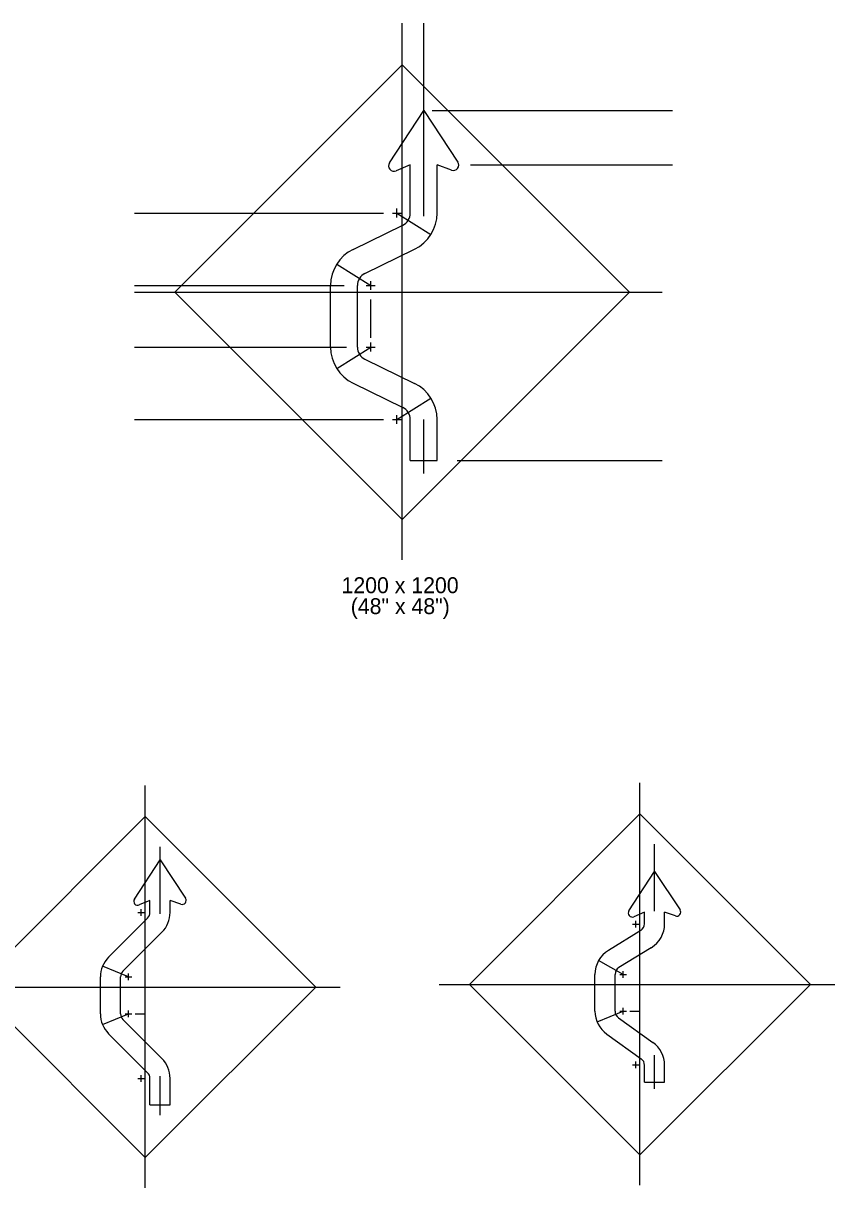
# Model space of a CAD drawing. Extents: x 0 to 0.249, y -0.213 to 0.259.
# Drawn here: x 0.1279 to 0.249, y -0.1781 to -0.0043 of the extents above; entities that cross this region are included whole.
import ezdxf

# ---------------------------------------------------------------- set-up
doc = ezdxf.new("R2010")
doc.units = 0
doc.layers.add('1', color=7, linetype='Continuous')
doc.layers.add('3', color=7, linetype='Continuous')

msp = doc.modelspace()

# ---------------------------------------------------------------- linework, layer by layer
at = {"layer": '1'}
for p, q in [((0.18253828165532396, -0.02516510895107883), (0.18764227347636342, -0.017349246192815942)), ((0.18764227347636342, -0.017349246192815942), (0.19273947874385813, -0.02503121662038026)), ((0.18891761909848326, -0.017334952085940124), (0.22476879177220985, -0.017334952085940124)), ((0.18564227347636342, -0.025454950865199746), (0.1835158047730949, -0.026340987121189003)), ((0.18564227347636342, -0.03264923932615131), (0.18564227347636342, -0.025454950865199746)), ((0.19180380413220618, -0.026226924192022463), (0.18964227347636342, -0.025454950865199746)), ((0.18964227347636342, -0.03264923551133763), (0.18964227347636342, -0.025454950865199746)), ((0.1946373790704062, -0.025454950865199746), (0.22476879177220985, -0.025454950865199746)), ((0.14447220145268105, -0.03264924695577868), (0.18163737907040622, -0.03264924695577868)), ((0.1829756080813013, -0.032649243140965), (0.18430893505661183, -0.032649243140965)), ((0.18364227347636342, -0.03331591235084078), (0.18364227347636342, -0.03198257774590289)), ((0.18364227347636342, -0.03264924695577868), (0.18873004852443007, -0.03582957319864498)), ((0.17711379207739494, -0.03805563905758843), (0.18451843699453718, -0.034447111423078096)), ((0.17886611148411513, -0.04165137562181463), (0.18627075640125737, -0.0380428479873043)), ((0.17465449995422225, -0.04026891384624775), (0.1797422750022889, -0.04344924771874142)), ((0.1797422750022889, -0.0441159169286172), (0.1797422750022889, -0.04278258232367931)), ((0.14447220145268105, -0.04344924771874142), (0.1757623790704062, -0.04344924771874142)), ((0.1737422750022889, -0.052649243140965), (0.1737422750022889, -0.0434492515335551)), ((0.1777422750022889, -0.052649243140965), (0.1777422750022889, -0.04344924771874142)), ((0.1790756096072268, -0.0434492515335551), (0.180408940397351, -0.0434492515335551)), ((0.1797422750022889, -0.05127372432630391), (0.1797422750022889, -0.04552372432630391)), ((0.1797422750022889, -0.053315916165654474), (0.1797422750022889, -0.05198257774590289)), ((0.14447220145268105, -0.05264924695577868), (0.17613737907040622, -0.05264924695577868)), ((0.17465449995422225, -0.05582958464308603), (0.1797422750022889, -0.05264924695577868)), ((0.17907561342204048, -0.052649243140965), (0.180408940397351, -0.052649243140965)), ((0.17886611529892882, -0.05444711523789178), (0.18627075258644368, -0.05805563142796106)), ((0.17711379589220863, -0.05804285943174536), (0.1845184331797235, -0.06165137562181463)), ((0.18364227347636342, -0.06344924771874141), (0.18873004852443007, -0.06026890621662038)), ((0.14447220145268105, -0.06344924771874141), (0.18163737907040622, -0.06344924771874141)), ((0.18297560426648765, -0.06344924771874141), (0.18430893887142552, -0.06344924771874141)), ((0.18364227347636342, -0.06411591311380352), (0.18364227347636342, -0.06278258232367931)), ((0.18564227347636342, -0.06954924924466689), (0.18564227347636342, -0.06344924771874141)), ((0.18964227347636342, -0.06954924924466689), (0.18964227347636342, -0.06344924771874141)), ((0.18564227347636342, -0.06954924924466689), (0.18964227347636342, -0.06954924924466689)), ((0.19261663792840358, -0.06954924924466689), (0.22322677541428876, -0.06954924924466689)), ((0.14445398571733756, -0.13503341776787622), (0.14828614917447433, -0.12916514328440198)), ((0.14828614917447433, -0.12916514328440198), (0.15209530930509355, -0.13490590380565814)), ((0.21828330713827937, -0.13678122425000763), (0.22211547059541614, -0.13091294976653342)), ((0.22211547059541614, -0.13091294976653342), (0.22592463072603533, -0.13665371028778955)), ((0.14678278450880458, -0.13525024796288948), (0.14518732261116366, -0.1359150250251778)), ((0.14678278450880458, -0.13702302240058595), (0.14678278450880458, -0.13525024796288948)), ((0.14978278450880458, -0.13702301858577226), (0.14978278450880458, -0.13522436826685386)), ((0.1513909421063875, -0.13579871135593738), (0.14978278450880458, -0.13522436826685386)), ((0.14498278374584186, -0.13702301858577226), (0.14598278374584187, -0.13702301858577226)), ((0.14548278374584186, -0.13752301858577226), (0.14548278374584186, -0.13652301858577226)), ((0.2206121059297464, -0.1369980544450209), (0.21901664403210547, -0.1376628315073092)), ((0.2206121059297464, -0.13871168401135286), (0.2206121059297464, -0.1369980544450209)), ((0.22361210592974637, -0.13871168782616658), (0.22361210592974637, -0.13697217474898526)), ((0.22522026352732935, -0.1375465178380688), (0.22361210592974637, -0.13697217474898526)), ((0.14061293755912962, -0.1436899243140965), (0.1464313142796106, -0.13787154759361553)), ((0.21881210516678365, -0.13877082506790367), (0.21981210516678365, -0.13877082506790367)), ((0.21931210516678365, -0.13927082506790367), (0.21931210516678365, -0.13827082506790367)), ((0.14273425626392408, -0.14581124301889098), (0.14855263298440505, -0.13999286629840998)), ((0.2200394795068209, -0.13973462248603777), (0.21521941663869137, -0.14269080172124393)), ((0.2216079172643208, -0.14229196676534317), (0.21678785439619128, -0.14524814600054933)), ((0.21741522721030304, -0.14627108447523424), (0.2137503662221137, -0.14421954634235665)), ((0.14358278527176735, -0.1466597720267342), (0.13970249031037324, -0.14505250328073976)), ((0.21741522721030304, -0.14677108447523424), (0.21741522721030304, -0.14577108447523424)), ((0.13938278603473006, -0.1521597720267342), (0.13938278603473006, -0.1466597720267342)), ((0.14238278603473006, -0.1521597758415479), (0.14238278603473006, -0.14665976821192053)), ((0.14308278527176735, -0.1466597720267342), (0.14408278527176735, -0.1466597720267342)), ((0.14358278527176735, -0.1471597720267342), (0.14358278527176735, -0.14615977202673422)), ((0.2132152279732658, -0.15177105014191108), (0.2132152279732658, -0.14627108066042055)), ((0.2162152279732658, -0.15177105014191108), (0.2162152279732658, -0.14627108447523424)), ((0.21691522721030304, -0.14627108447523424), (0.21791522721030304, -0.14627108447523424)), ((0.13970249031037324, -0.15376704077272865), (0.14358278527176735, -0.1521597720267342)), ((0.14308278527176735, -0.1521597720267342), (0.14408278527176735, -0.1521597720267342)), ((0.14358278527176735, -0.1526597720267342), (0.14358278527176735, -0.1516597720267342)), ((0.14458906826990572, -0.1521597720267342), (0.14608278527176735, -0.1521597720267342)), ((0.213534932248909, -0.15337835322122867), (0.21741522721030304, -0.15177108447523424)), ((0.2167168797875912, -0.15274691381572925), (0.2218594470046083, -0.15642704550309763)), ((0.21691522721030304, -0.15177108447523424), (0.21791522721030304, -0.15177108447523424)), ((0.21741522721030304, -0.15227108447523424), (0.21741522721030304, -0.15127108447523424)), ((0.21842151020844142, -0.15177108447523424), (0.21991522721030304, -0.15177108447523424)), ((0.14855263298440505, -0.15882667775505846), (0.14273425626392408, -0.15300830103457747)), ((0.1464313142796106, -0.16094799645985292), (0.14061293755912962, -0.15512961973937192)), ((0.2149710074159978, -0.15518657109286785), (0.22011357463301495, -0.1588667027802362)), ((0.21881534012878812, -0.15976931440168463), (0.21981534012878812, -0.15976931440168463)), ((0.21931534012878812, -0.16026931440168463), (0.21931534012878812, -0.15926931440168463)), ((0.22061522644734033, -0.1623710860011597), (0.22061522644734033, -0.15984256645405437)), ((0.22361522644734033, -0.1623710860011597), (0.22361522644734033, -0.15984256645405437)), ((0.14548278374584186, -0.16229652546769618), (0.14548278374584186, -0.16129652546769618)), ((0.14498278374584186, -0.16179652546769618), (0.14598278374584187, -0.16179652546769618)), ((0.14678278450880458, -0.1657597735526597), (0.14678278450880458, -0.16179652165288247)), ((0.14978278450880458, -0.1657597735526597), (0.14978278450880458, -0.16179652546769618)), ((0.22061522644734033, -0.1623710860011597), (0.22361522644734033, -0.1623710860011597)), ((0.14678278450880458, -0.1657597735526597), (0.14978278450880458, -0.1657597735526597))]:
    msp.add_line(p, q, dxfattribs=at)
for centre, radius, start, end in [((0.18320810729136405, -0.025602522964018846), 0.0008, 146.8542682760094, 292.6199860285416), ((0.19207287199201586, -0.025473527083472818), 0.0008, 250.34626894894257, 33.56539330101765), ((0.18364227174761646, -0.032649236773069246), 0.002, 295.9814970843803, 0), ((0.18364227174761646, -0.032649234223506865), 0.006, 295.98148554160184, 0), ((0.17974227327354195, -0.04344924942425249), 0.006, 115.98148554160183, 180), ((0.17974227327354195, -0.04344924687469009), 0.002, 115.9814970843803, 180), ((0.17974227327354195, -0.05264924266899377), 0.006, 180, 244.01855564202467), ((0.17974227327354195, -0.05264924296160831), 0.002, 180, 244.01856228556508), ((0.18364227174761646, -0.06344924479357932), 0.006, 0, 64.01855564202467), ((0.18364227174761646, -0.06344924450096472), 0.002, 1.4210854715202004e-14, 64.0185622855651), ((0.14495655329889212, -0.13536117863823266), 0.0006, 146.8886580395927, 292.619864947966), ((0.15159274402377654, -0.13523366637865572), 0.0006, 250.34617594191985, 33.111341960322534), ((0.14558278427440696, -0.13702302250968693), 0.0012, 315, 0), ((0.14558278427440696, -0.13702301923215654), 0.004200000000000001, 315, 0), ((0.2187858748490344, -0.13710898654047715), 0.0005999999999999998, 146.8886580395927, 292.619864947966), ((0.2254220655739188, -0.13698147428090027), 0.0006, 250.34617594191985, 33.111341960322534), ((0.21941210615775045, -0.1387116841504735), 0.0012, 301.52108273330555, 0), ((0.21941210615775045, -0.13871168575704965), 0.004200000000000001, 301.521084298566, 0), ((0.14358278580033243, -0.1466597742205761), 0.004200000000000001, 135, 180), ((0.21741522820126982, -0.14627108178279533), 0.004200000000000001, 121.52108429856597, 180), ((0.14358278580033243, -0.14665977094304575), 0.0012, 135, 180), ((0.21741522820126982, -0.1462710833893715), 0.0012, 121.52108273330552, 180), ((0.14358278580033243, -0.15215977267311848), 0.004200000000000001, 180.00000000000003, 225.00000000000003), ((0.14358278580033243, -0.15215977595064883), 0.0012, 180.00000000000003, 225.00000000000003), ((0.21741522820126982, -0.15177104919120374), 0.004200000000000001, 180, 234.41167335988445), ((0.21741522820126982, -0.15177104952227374), 0.0012, 180, 234.41167410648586), ((0.21941522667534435, -0.1598425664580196), 0.004200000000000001, 360, 54.41167335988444), ((0.14558278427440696, -0.16179652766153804), 0.004200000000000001, 0, 45), ((0.21941522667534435, -0.1598425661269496), 0.0012, 0, 54.41167410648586), ((0.14558278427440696, -0.1617965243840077), 0.0012, 0, 45)]:
    msp.add_arc(centre, radius, start, end, dxfattribs=at)
at = {"layer": '3'}
for p, q in [((0.18444227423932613, -0.08438583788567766), (0.18444227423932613, -0.004316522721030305)), ((0.18764227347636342, -0.03308924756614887), (0.18764227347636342, -0.004316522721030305)), ((0.1505011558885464, -0.04444924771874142), (0.18444227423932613, -0.01050812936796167)), ((0.2183833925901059, -0.04444924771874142), (0.18444227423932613, -0.01050812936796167)), ((0.14447220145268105, -0.04444924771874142), (0.22322677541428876, -0.04444924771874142)), ((0.18444227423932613, -0.07839036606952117), (0.1505011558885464, -0.04444924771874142)), ((0.18444227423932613, -0.07839036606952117), (0.2183833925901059, -0.04444924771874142)), ((0.18764227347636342, -0.07149671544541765), (0.18764227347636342, -0.06344924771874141)), ((0.14608278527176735, -0.1781122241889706), (0.14608278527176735, -0.11806021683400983)), ((0.21991522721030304, -0.17772353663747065), (0.21991522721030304, -0.11767152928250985)), ((0.12062693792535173, -0.1481597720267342), (0.14608278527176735, -0.12270392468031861)), ((0.17153863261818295, -0.1481597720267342), (0.14608278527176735, -0.12270392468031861)), ((0.19445937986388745, -0.14777108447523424), (0.21991522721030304, -0.12231523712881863)), ((0.24537107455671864, -0.14777108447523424), (0.21991522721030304, -0.12231523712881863)), ((0.22211522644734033, -0.13684762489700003), (0.22211522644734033, -0.12684762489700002)), ((0.14828278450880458, -0.13723631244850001), (0.14828278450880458, -0.1272363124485)), ((0.1445, -0.134875), (0.1445, -0.134875)), ((0.11610522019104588, -0.1481597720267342), (0.17517117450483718, -0.1481597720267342)), ((0.14608278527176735, -0.17361561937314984), (0.12062693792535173, -0.1481597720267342)), ((0.14608278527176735, -0.17361561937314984), (0.17153863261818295, -0.1481597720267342)), ((0.18993766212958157, -0.14777108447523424), (0.24900361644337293, -0.14777108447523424)), ((0.21991522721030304, -0.17322693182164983), (0.19445937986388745, -0.14777108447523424)), ((0.21991522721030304, -0.17322693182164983), (0.24537107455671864, -0.14777108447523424)), ((0.22211522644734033, -0.16336770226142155), (0.22211522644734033, -0.15831113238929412)), ((0.14828278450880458, -0.1672636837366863), (0.14828278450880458, -0.1614863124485))]:
    msp.add_line(p, q, dxfattribs=at)

# ---------------------------------------------------------------- texts
for s, p in [('1200 x 1200', (0.175375, -0.089375)), ('(48" x 48")', (0.17675, -0.0925))]:
    msp.add_text(s, height=0.0023752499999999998, dxfattribs=at).set_placement(p)

doc.saveas('drawing.dxf')
